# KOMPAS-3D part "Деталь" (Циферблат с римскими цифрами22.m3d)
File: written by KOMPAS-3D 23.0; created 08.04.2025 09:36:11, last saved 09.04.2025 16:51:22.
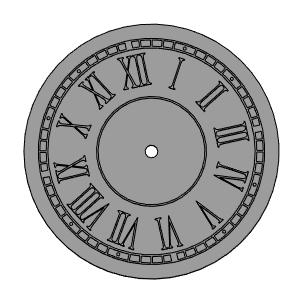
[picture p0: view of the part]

Document properties: Автор: sss.aaa25@outlook.com; Полное имя файла: D:\Downloads\3864552-vms\Циферблат с римскими цифрами22.m3d

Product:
- Part/product: Деталь
    Масса: 0.336791

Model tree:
1. Эскиз:3
2. Элемент выдавливания:2
     Расстояние 2 = 2
3. Эскиз:4  (with: Элемент выдавливания:2)
4. Элемент выдавливания:3
     Расстояние 1 = 1
5. Эскиз:5  (with: Элемент выдавливания:2, Элемент выдавливания:3)
6. Элемент выдавливания:4
     Расстояние 2 = 10
7. Эскиз:6  (with: Элемент выдавливания:2)
8. Элемент выдавливания:5
     Толщина стенки 1 = 4; Расстояние 1 = 1
9. Массив по концентрической сетке:1  (with: Элемент выдавливания:5)  (4 pattern instances)
     Шаг 2 = 360
10. Эскиз:8  (with: Элемент выдавливания:2)
11. Элемент выдавливания:11
     Расстояние 1 = 2
12. Эскиз:9  (with: Элемент выдавливания:2)
13. Элемент выдавливания:12
     Расстояние 1 = 1
14. Массив по концентрической сетке:3  (with: Элемент выдавливания:12)  (60 pattern instances)
     Шаг 2 = 360
15. Эскиз:10  (with: Элемент выдавливания:3)
16. Элемент выдавливания:13
     Расстояние 2 = 2
17. Массив по концентрической сетке:4  (with: Элемент выдавливания:13)  (12 pattern instances)
     Шаг 2 = 360
18. Эскиз:11  (with: Элемент выдавливания:3, Элемент выдавливания:12, Элемент выдавливания:13)
19. Элемент выдавливания:14
     Расстояние 2 = 1
20. Массив по концентрической сетке:5  (with: Элемент выдавливания:14)  (12 pattern instances)
     Шаг 2 = 360
21. Эскиз:12  (with: Элемент выдавливания:3, Элемент выдавливания:5)
22. Элемент выдавливания:15
     Расстояние 2 = 1
23. Массив по концентрической сетке:6  (with: Элемент выдавливания:15)  (4 pattern instances)
     Шаг 2 = 360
